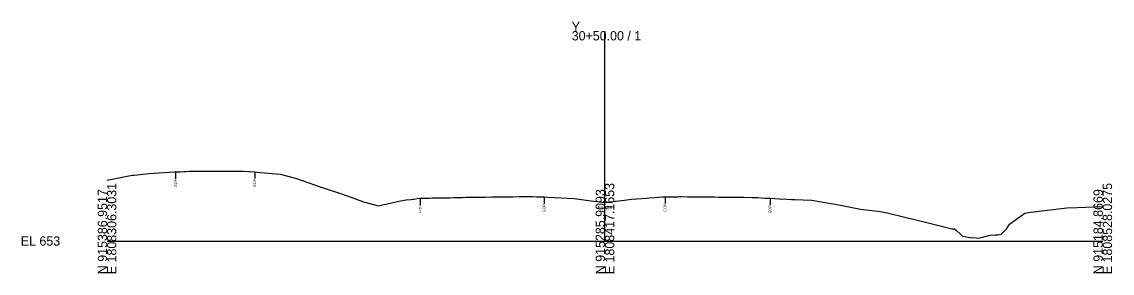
# Model space of a CAD drawing. Extents: x -26 to 3303, y -30 to 9580.
# Drawn here: x 1974.3 to 2302.8, y 490.3 to 566 of the extents above; entities that cross this region are included whole.
import ezdxf

# ---------------------------------------------------------------- set-up
doc = ezdxf.new("R2010")
doc.units = 0
for name, color, linetype in [('Exist Cross Section Cell', 7, 'Continuous'), ('Exist XS Center Line Elevation Label', 7, 'Continuous'), ('Exist XS Ground Line', 7, 'Continuous'), ('Old_Level_10', 7, 'Continuous')]:
    doc.layers.add(name, color=color, linetype=linetype)

msp = doc.modelspace()

# ---------------------------------------------------------------- linework, layer by layer
at = {"layer": 'Exist Cross Section Cell'}
for p, q in [((2150, 500), (2150, 563.22)), ((2000, 500), (2150, 500)), ((2150, 500), (2300, 500))]:
    msp.add_line(p, q, dxfattribs=at)
at = {"layer": 'Exist XS Ground Line'}
msp.add_lwpolyline([(2000, 518.31), (2005, 519.31), (2007.54, 519.79), (2008.18, 519.87), (2012.66, 520.36), (2020.27, 520.8), (2020.66, 520.82), (2022.13, 520.86), (2023.16, 520.89), (2023.72, 520.92), (2024.73, 521), (2026.05, 521), (2026.71, 521), (2027.42, 521), (2029.38, 521.01), (2031.14, 521.02), (2032.45, 521.03), (2033.33, 521.03), (2034.85, 521.04), (2036.17, 521.04), (2038.57, 521.06), (2039.07, 521.07), (2039.52, 521.07), (2041.05, 521.07), (2042.61, 520.91), (2043, 520.9), (2044.49, 520.83), (2045.18, 520.77), (2046.25, 520.65), (2052.13, 520.12), (2056.39, 519.03), (2057.09, 518.82), (2059.12, 518.11), (2064.17, 516.31), (2069.7, 514.52), (2072.65, 513.53), (2077.29, 511.83), (2079.84, 511.06), (2081.72, 510.56), (2088.45, 512.07), (2090.07, 512.37), (2091.64, 512.55), (2091.99, 512.59), (2092.52, 512.65), (2093.43, 512.77), (2094.34, 512.88), (2095.08, 512.9), (2097.06, 512.94), (2097.95, 512.96), (2100.48, 512.98), (2101.02, 512.99), (2101.63, 513), (2102.8, 513.01), (2103.42, 513.05), (2104.35, 513.11), (2105.36, 513.12), (2107.21, 513.15), (2108.09, 513.17), (2109.07, 513.18), (2110.58, 513.2), (2111.62, 513.21), (2112.8, 513.23), (2113.41, 513.23), (2113.95, 513.25), (2115.94, 513.29), (2116.82, 513.29), (2117.34, 513.3), (2120.18, 513.33), (2120.75, 513.34), (2122.25, 513.35), (2124.12, 513.37), (2125.85, 513.39), (2127.68, 513.41), (2128.21, 513.37), (2129.34, 513.29), (2131.16, 513.29), (2131.68, 513.28), (2132.77, 513.22), (2140.73, 512.83), (2145.89, 512.15), (2149.89, 511.58), (2155.86, 512.33), (2158.02, 512.62), (2162.54, 512.94), (2163.47, 513), (2164.89, 513.09), (2167.31, 513.26), (2168.11, 513.31), (2168.5, 513.31), (2170.02, 513.3), (2171.48, 513.34), (2171.92, 513.35), (2172.47, 513.38), (2173, 513.37), (2174.84, 513.35), (2175.86, 513.34), (2177.11, 513.33), (2178.23, 513.32), (2178.89, 513.31), (2179.6, 513.3), (2181.63, 513.27), (2182.42, 513.27), (2182.98, 513.26), (2184.19, 513.24), (2185.03, 513.23), (2185.97, 513.22), (2187.02, 513.21), (2187.76, 513.2), (2188.44, 513.2), (2190.73, 513.17), (2191.78, 513.16), (2194.41, 513.12), (2195.02, 513.11), (2195.75, 513.1), (2196.07, 513.07), (2198.16, 512.92), (2198.76, 512.89), (2199.76, 512.86), (2202.61, 512.73), (2204.84, 512.62), (2206.24, 512.55), (2207.19, 512.5), (2212.26, 512.26), (2212.82, 512.19), (2218.15, 511.3), (2219.9, 511.01), (2221.49, 510.71), (2226.98, 509.63), (2233, 508.84), (2235.02, 508.5), (2247.84, 505.33), (2248.55, 505.14), (2254.55, 503.64), (2255.35, 503.68), (2255.9, 503.15), (2256.99, 502.14), (2257.74, 501.48), (2258.48, 501.31), (2260.09, 501.1), (2261.82, 500.94), (2262.6, 500.84), (2263.8, 501.18), (2266.12, 501.71), (2267.7, 501.82), (2268.41, 501.81), (2269.43, 502.09), (2270.5, 503.14), (2271.1, 503.75), (2271.87, 505.05), (2276.53, 508.4), (2277.53, 508.6), (2289.14, 510), (2292.38, 510.1), (2300, 510.4)], dxfattribs=at)
at = {"layer": 'Old_Level_10'}
for p, q in [((2020.66, 520.82), (2020.66, 518.77)), ((2044.49, 520.83), (2044.49, 518.78)), ((2094.34, 512.88), (2094.34, 510.83)), ((2131.68, 513.28), (2131.68, 511.23)), ((2168.11, 513.31), (2168.11, 511.26)), ((2199.76, 512.86), (2199.76, 510.81))]:
    msp.add_line(p, q, dxfattribs=at)

# ---------------------------------------------------------------- texts
at = {"layer": 'Exist Cross Section Cell'}
for s, p in [('Y', (2140, 563.22)), ('30+50.00 / 1', (2140, 560.42)), ('EL 653', (1974, 498.6))]:
    msp.add_text(s, height=2.8, dxfattribs=at).set_placement(p)
for s, p in [('E 1808306.3031', (2002.8, 490)), ('E 1808417.1653', (2152.8, 490)), ('E 1808528.0275', (2302.8, 490)), ('N 915386.9517', (2000, 490)), ('N 915285.9093', (2150, 490)), ('N 915184.8669', (2300, 490))]:
    msp.add_text(s, height=2.8, rotation=90, dxfattribs=at).set_placement(p)
at = {"layer": 'Exist XS Center Line Elevation Label'}
msp.add_text('664.59', height=1, dxfattribs=at).set_placement((2147.87, 509.59))
at = {"layer": 'Old_Level_10'}
for p in [(2021.06, 516.37), (2044.88, 516.38), (2094.73, 508.43), (2132.07, 508.83), (2168.5, 508.87), (2200.15, 508.41)]:
    msp.add_text('EOP', height=0.787, rotation=90, dxfattribs=at).set_placement(p)

doc.saveas('drawing.dxf')
